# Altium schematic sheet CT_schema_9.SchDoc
size 254 x 194 mm
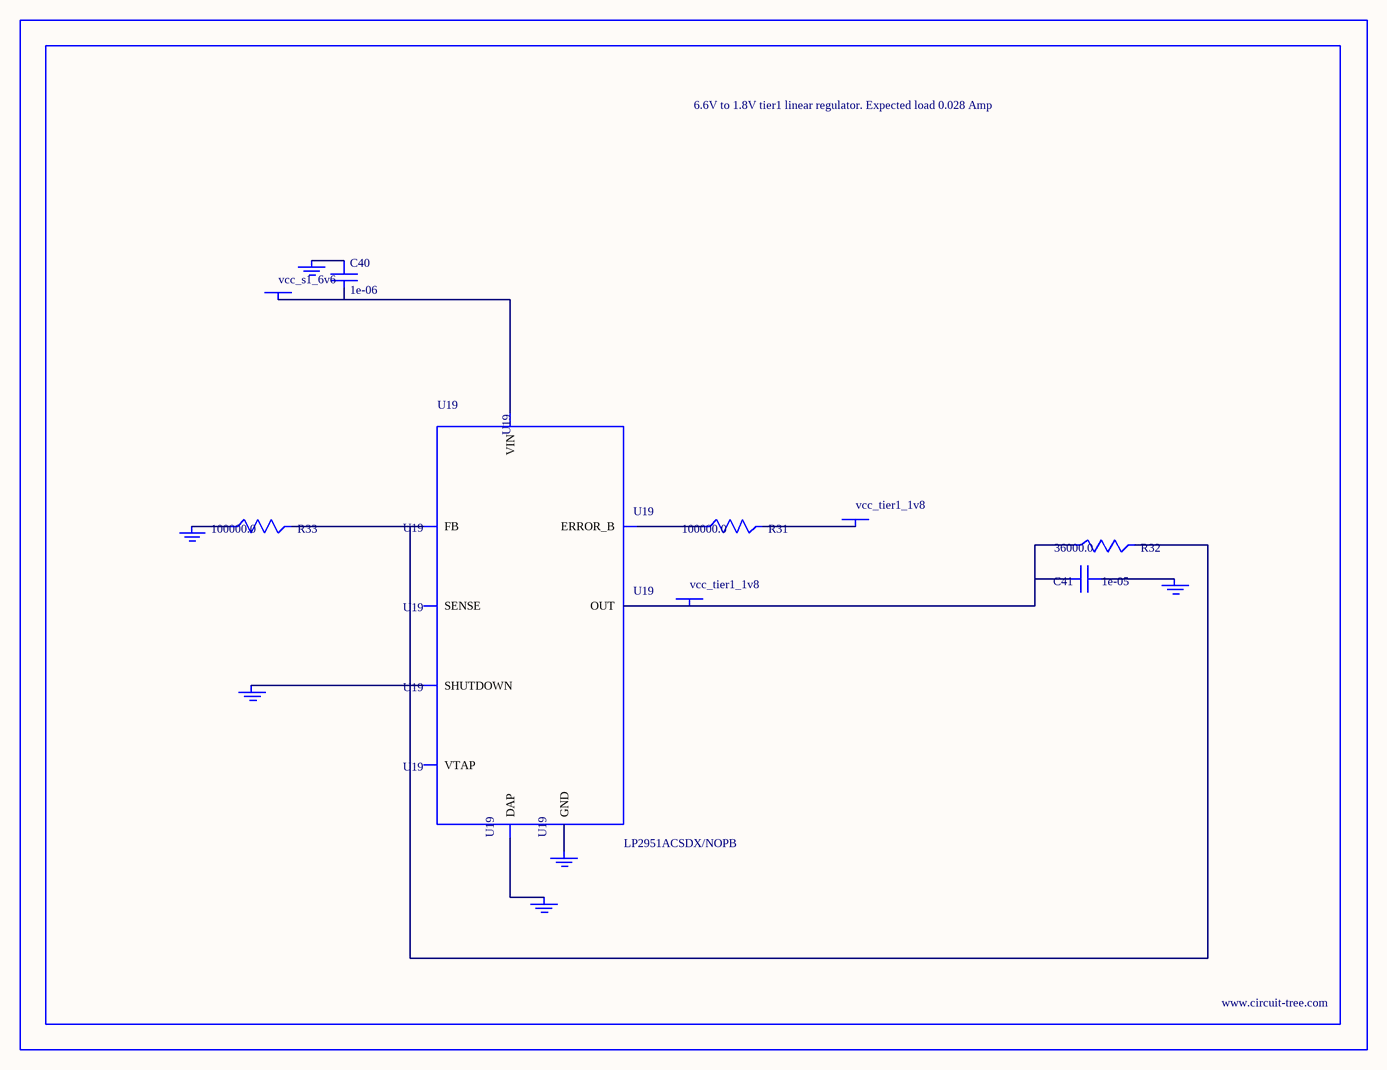
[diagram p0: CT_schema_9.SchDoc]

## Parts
BORDER8  (no value)
C40  1e-06  [C0603]
C41  1e-05  [C0805]
GND_INSTANCE_8_0  (no value)
GND_INSTANCE_8_1  (no value)
GND_INSTANCE_8_2  (no value)
GND_INSTANCE_8_3  (no value)
GND_INSTANCE_8_4  (no value)
GND_INSTANCE_8_5  (no value)
POWER_INSTANCE_8_0  vcc_tier1_1v8
POWER_INSTANCE_8_1  vcc_s1_6v6
POWER_INSTANCE_8_2  vcc_tier1_1v8
R31  100000.0  [R0603]
R32  36000.0  [R0603]
R33  100000.0  [R0603]
U19  LP2951ACSDX/NOPB  [WSON-8]

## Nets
NetC40_1: C40.1 GND_INSTANCE_8_3.0(GND)
NetC40_2: C40.2 POWER_INSTANCE_8_1.0(PWR) U19.8(VIN)
NetC41_1: C41.1 GND_INSTANCE_8_0.0(GND)
NetC41_2: C41.2 POWER_INSTANCE_8_2.0(PWR) R32.1 U19.1(OUT)
NetGND_INSTANCE_8_1_0: GND_INSTANCE_8_1.0(GND) U19.3(SHUTDOWN)
NetGND_INSTANCE_8_2_0: GND_INSTANCE_8_2.0(GND) R33.1
NetGND_INSTANCE_8_4_0: GND_INSTANCE_8_4.0(GND) U19.PAD(DAP)
NetGND_INSTANCE_8_5_0: GND_INSTANCE_8_5.0(GND) U19.4(GND)
NetPOWER_INSTANCE_8_0_0: POWER_INSTANCE_8_0.0(PWR) R31.2
NetR31_1: R31.1 U19.5(ERROR_B)
NetR32_2: R32.2 R33.2 U19.7(FB)

Not connected (* = marked no-connect by the designer): U19 2(SENSE) 6(VTAP)

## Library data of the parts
BORDER8 = BORDER_PAGE8
C40 = C0603C105K3RACTU
C41 = GRM219R60J106ME19D
GND_INSTANCE_8_0-GND_INSTANCE_8_5 = GND
POWER_INSTANCE_8_0-POWER_INSTANCE_8_2 = PWR
R31 R33 = RC0603JR-07100KL
R32 = RC0603JR-0736KL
